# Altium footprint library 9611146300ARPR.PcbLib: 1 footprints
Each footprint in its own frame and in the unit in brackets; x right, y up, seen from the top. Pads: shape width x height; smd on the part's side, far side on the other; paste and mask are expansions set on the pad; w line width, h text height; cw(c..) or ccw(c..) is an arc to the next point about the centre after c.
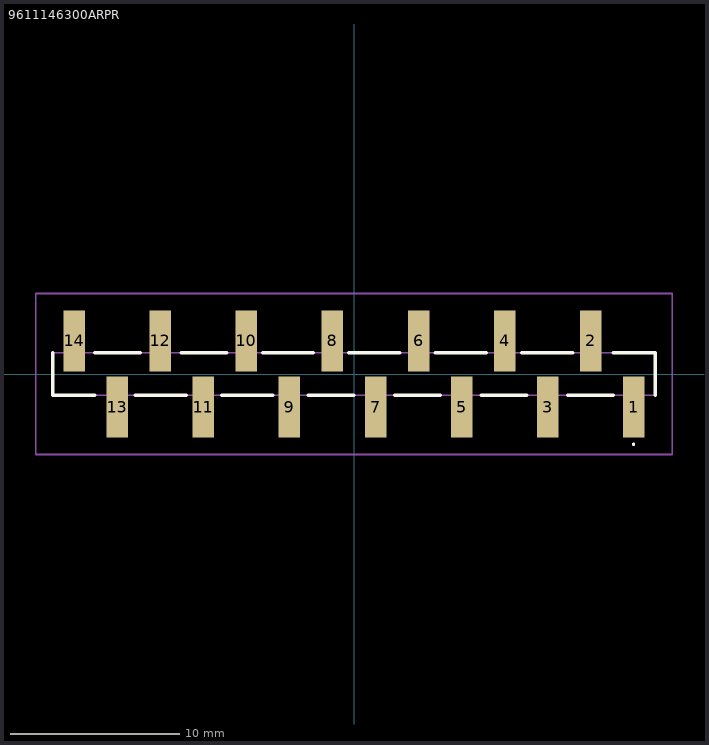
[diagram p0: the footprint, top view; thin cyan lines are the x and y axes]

## 9611146300ARPR [mm]
pads (14):
  rect 1.27x3.6 smd: 1(16.51,-1.95) 2(13.97,1.95) 3(11.43,-1.95) 4(8.89,1.95) 5(6.35,-1.95) 6(3.81,1.95) 7(1.27,-1.95) 8(-1.27,1.95) 9(-3.81,-1.95) 10(-6.35,1.95) 11(-8.89,-1.95) 12(-11.43,1.95) 13(-13.97,-1.95) 14(-16.51,1.95)
Top Overlay:
  lines w0.1: 16.5,-4.2 16.5,-4.2 ; 16.5,-4.2 ccw(c16.5,-4.15) 16.5,-4.1 ; 16.5,-4.2 cw(c16.5,-4.15) 16.5,-4.1 ; 16.5,-4.1 16.5,-4.1
  lines w0.2: -17.78,1.25 -17.78,-1.25 -15.3,-1.25 ; -15.3,1.25 -12.6,1.25 ; -12.9,-1.25 -9.9,-1.25 ; -10.2,1.25 -7.5,1.25 ; -7.8,-1.25 -4.8,-1.25 ; -5.4,1.25 -2.4,1.25 ; -2.7,-1.25 0,-1.25 ; -0.3,1.25 2.7,1.25 ; 2.4,-1.25 5.1,-1.25 ; 4.8,1.25 7.8,1.25 ; 7.5,-1.25 10.2,-1.25 ; 9.9,1.25 12.9,1.25 ; 12.6,-1.25 15.3,-1.25 ; 15.3,1.25 17.78,1.25 17.78,-1.25
Mechanical 15:
  lines w0.1: -17.78,-1.25 17.78,-1.25 17.78,1.25 -17.78,1.25 -17.78,-1.25
Mechanical 20:
  lines w0.1: -18.78,-4.75 18.78,-4.75 18.78,4.75 -18.78,4.75 -18.78,-4.75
